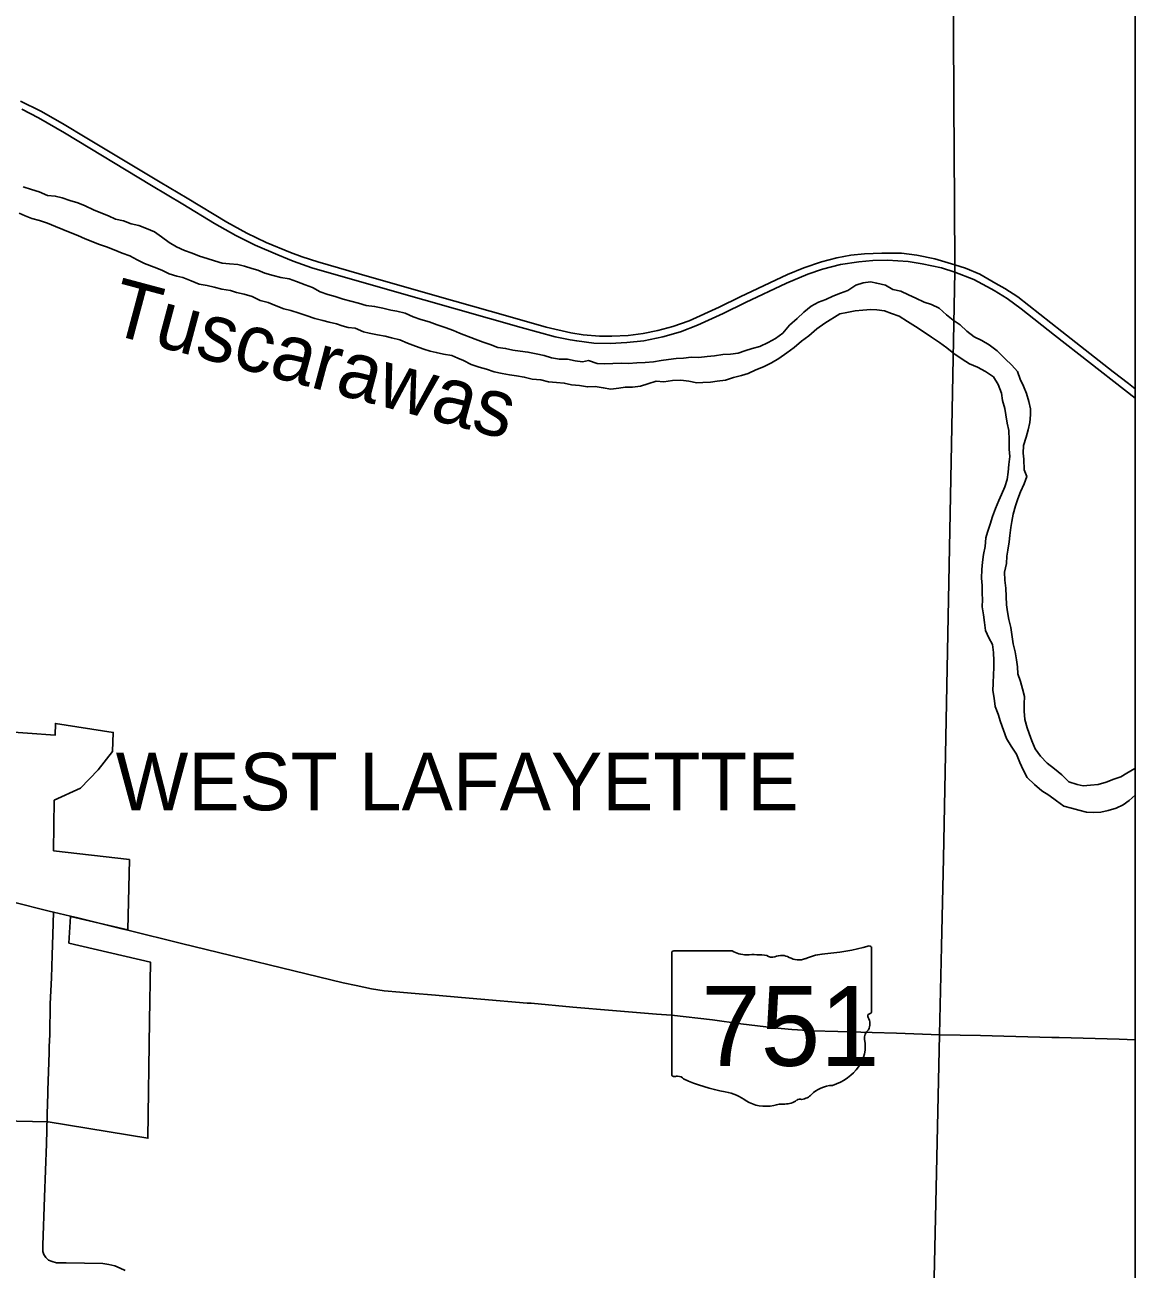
# Model space of a CAD drawing. Extents: x -6.3 to 34, y 0 to 22.
# Drawn here: x 10.934 to 12.189, y 11.89 to 13.296 of the extents above; entities that cross this region are included whole.
import ezdxf

# ---------------------------------------------------------------- set-up
doc = ezdxf.new("R2010")
doc.units = 0
for name, color, linetype in [('GM_X_Corporation', 7, 'Continuous'), ('GM_X_Corporation_Text', 7, 'Continuous'), ('GM_X_Major_River', 7, 'Continuous'), ('GM_X_Major_River_Text', 7, 'Continuous'), ('GM_X_State_Route', 7, 'Continuous'), ('GM_X_State_Shield', 7, 'Continuous'), ('GM_X_Township', 7, 'Continuous'), ('GM_X_US_Route', 7, 'Continuous'), ('SH_Text', 7, 'Continuous')]:
    doc.layers.add(name, color=color, linetype=linetype)

msp = doc.modelspace()

# ---------------------------------------------------------------- linework, layer by layer
at = {"layer": 'GM_X_Corporation'}
msp.add_lwpolyline([(10.8744, 12.5005), (10.9685, 12.4936), (10.9687, 12.5071), (11.0342, 12.4968), (11.0334, 12.4753), (11.0172, 12.4545), (10.997, 12.4338), (10.9674, 12.4203), (10.9667, 12.3631), (11.0524, 12.3532), (11.0506, 12.2737), (10.9859, 12.2887), (10.9841, 12.2589), (11.0763, 12.2372), (11.0753, 12.1709), (11.0733, 12.0382), (10.9606, 12.0567), (10.8895, 12.0582)], dxfattribs=at)
at = {"layer": 'GM_X_Major_River'}
for points in [[(11.6787, 12.9197), (11.6702, 12.9193), (11.6616, 12.9182), (11.6534, 12.9173), (11.6446, 12.9156), (11.6353, 12.9147), (11.6259, 12.9144), (11.6166, 12.9137), (11.6083, 12.9142), (11.5988, 12.9138), (11.5897, 12.9134), (11.5809, 12.9136), (11.5713, 12.9171), (11.5646, 12.9157), (11.556, 12.9169), (11.5474, 12.9187), (11.5384, 12.9186), (11.5295, 12.9203), (11.521, 12.9228), (11.5121, 12.9247), (11.5028, 12.9267), (11.494, 12.9277), (11.4857, 12.9289), (11.4776, 12.9308), (11.4688, 12.932), (11.4602, 12.9351), (11.4522, 12.9378), (11.4431, 12.9411), (11.4254, 12.9482), (11.4186, 12.9509), (11.4092, 12.9545), (11.4001, 12.9575), (11.391, 12.9608), (11.3819, 12.9635), (11.3731, 12.9663), (11.364, 12.9708), (11.3546, 12.9728), (11.3479, 12.974), (11.3388, 12.9763), (11.3295, 12.9782), (11.3201, 12.9794), (11.3113, 12.9819), (11.3027, 12.9842), (11.2939, 12.9864), (11.2851, 12.9894), (11.2765, 12.9917), (11.2679, 12.9947), (11.2593, 12.9995), (11.251, 13.0028), (11.2414, 13.0063), (11.233, 13.0096), (11.2237, 13.011), (11.2149, 13.013), (11.2055, 13.016), (11.1974, 13.0193), (11.1909, 13.0211), (11.1826, 13.0236), (11.1748, 13.0256), (11.1655, 13.0262), (11.1572, 13.0272), (11.1486, 13.0297), (11.1401, 13.0324), (11.1317, 13.0352), (11.1232, 13.0385), (11.1146, 13.0415), (11.1055, 13.0455), (11.0974, 13.0506), (11.0888, 13.057), (11.0807, 13.0624), (11.0718, 13.0662), (11.063, 13.0695), (11.0544, 13.0717), (11.0458, 13.075), (11.0367, 13.077), (11.0287, 13.0805), (11.0203, 13.084), (11.012, 13.0873), (11.0026, 13.0919), (10.994, 13.0954), (10.9852, 13.0979), (10.9766, 13.1009), (10.9686, 13.1029), (10.9598, 13.1034), (10.9504, 13.1079), (10.9416, 13.1104), (10.9325, 13.1134)], [(10.9279, 13.0838), (10.9347, 13.0807), (10.9422, 13.0777), (10.9508, 13.0754), (10.9599, 13.0722), (10.9687, 13.0684), (10.9773, 13.0651), (10.9856, 13.0618), (10.994, 13.0583), (11.0026, 13.0547), (11.0111, 13.0512), (11.0176, 13.0484), (11.0265, 13.0454), (11.0353, 13.0421), (11.0442, 13.0386), (11.0528, 13.0353), (11.0611, 13.031), (11.0694, 13.0269), (11.0804, 13.0226), (11.0889, 13.0191), (11.0975, 13.0151), (11.1061, 13.0123), (11.1129, 13.0111), (11.1222, 13.0073), (11.1311, 13.0032), (11.1402, 13.002), (11.1482, 13), (11.157, 12.9976), (11.1666, 12.9961), (11.1734, 12.9941), (11.1822, 12.9921), (11.1913, 12.9896), (11.2002, 12.9851), (11.2093, 12.9828), (11.2181, 12.9788), (11.227, 12.9755), (11.235, 12.9735), (11.2441, 12.9705), (11.2522, 12.968), (11.2618, 12.9645), (11.2711, 12.9622), (11.2781, 12.9605), (11.2865, 12.9585), (11.293, 12.9563), (11.2995, 12.9543), (11.3075, 12.9536), (11.3169, 12.9495), (11.3234, 12.948), (11.3327, 12.9463), (11.3413, 12.9446), (11.3485, 12.9429), (11.3579, 12.9404), (11.3665, 12.9368), (11.3758, 12.9333), (11.3852, 12.93), (11.3922, 12.9275), (11.3992, 12.9263), (11.4075, 12.9243), (11.4169, 12.9226), (11.4236, 12.9198), (11.4301, 12.9173), (11.4387, 12.9127), (11.4476, 12.9097), (11.4559, 12.9075), (11.4647, 12.9042), (11.4736, 12.9025), (11.4821, 12.901), (11.4899, 12.8998), (11.4987, 12.8984), (11.5076, 12.8961), (11.5174, 12.8952), (11.526, 12.8932), (11.5351, 12.8923), (11.5439, 12.8916), (11.5522, 12.8896), (11.561, 12.8889), (11.5701, 12.8872), (11.5789, 12.8878), (11.5879, 12.8864), (11.5963, 12.8847)], [(12.1236, 12.4382), (12.1142, 12.4412), (12.1061, 12.4489), (12.098, 12.4556), (12.0896, 12.462), (12.082, 12.4699), (12.076, 12.4785), (12.0722, 12.4872), (12.0693, 12.4955), (12.0669, 12.5022), (12.0644, 12.5113), (12.0635, 12.5207), (12.0637, 12.5292), (12.0639, 12.5375), (12.0617, 12.5463), (12.0595, 12.5544), (12.0566, 12.5629), (12.0562, 12.571), (12.0548, 12.579), (12.0534, 12.5881), (12.0513, 12.5971), (12.0484, 12.6153), (12.0463, 12.6244), (12.0446, 12.6332), (12.0437, 12.6412), (12.0431, 12.6503), (12.0427, 12.6599), (12.0419, 12.669), (12.0415, 12.6781), (12.0435, 12.6877), (12.0439, 12.696), (12.0451, 12.7028), (12.0465, 12.7122), (12.0472, 12.7192), (12.0484, 12.7283), (12.0496, 12.7351), (12.0511, 12.7434), (12.0536, 12.7528), (12.0566, 12.7609), (12.0593, 12.7689), (12.0636, 12.7776), (12.0666, 12.7862), (12.0636, 12.7934), (12.0632, 12.8056), (12.0626, 12.8123), (12.0628, 12.8212), (12.0659, 12.8306), (12.0681, 12.8389), (12.0701, 12.847), (12.0707, 12.8556), (12.0707, 12.8626), (12.0687, 12.8709), (12.0661, 12.8797), (12.0628, 12.888), (12.0591, 12.8962), (12.0562, 12.9048), (12.0496, 12.9117), (12.042, 12.9191), (12.0329, 12.9279), (12.024, 12.935), (12.0156, 12.9399), (12.007, 12.9439), (11.9987, 12.9503), (11.9913, 12.9575), (11.9835, 12.9626), (11.9757, 12.9688), (11.9675, 12.9762), (11.959, 12.9803), (11.9504, 12.983), (11.941, 12.9876), (11.9327, 12.9914), (11.9241, 12.9955), (11.9152, 12.9974), (11.9069, 13.0024), (11.897, 13.0045), (11.89, 13.006), (11.8818, 13.0049), (11.8735, 13.0022), (11.8643, 12.9961), (11.856, 12.9931), (11.8472, 12.9897), (11.8395, 12.9859), (11.8313, 12.983), (11.8228, 12.9787), (11.8146, 12.9716), (11.8071, 12.9645), (11.7984, 12.9569), (11.791, 12.9482), (11.7825, 12.9419), (11.7743, 12.9374), (11.765, 12.9329), (11.7563, 12.9307), (11.748, 12.928), (11.7403, 12.9256), (11.7317, 12.9244), (11.7229, 12.9238), (11.7136, 12.9224), (11.7054, 12.9218), (11.696, 12.9206), (11.6872, 12.921), (11.6787, 12.9197)], [(11.5963, 12.8847), (11.6056, 12.8858), (11.6128, 12.8869), (11.6211, 12.887), (11.6301, 12.8882), (11.6384, 12.8906), (11.6477, 12.8936), (11.6562, 12.8932), (11.6663, 12.8946), (11.6754, 12.8949), (11.6847, 12.8937), (11.6935, 12.892), (11.7005, 12.8921), (11.7091, 12.8925), (11.7168, 12.8936), (11.7259, 12.895), (11.7352, 12.898), (11.7442, 12.9001), (11.7517, 12.9026), (11.7604, 12.9066), (11.7689, 12.9098), (11.7779, 12.9146), (11.7862, 12.9193), (11.7954, 12.9259), (11.8036, 12.932), (11.8121, 12.9391), (11.8203, 12.9449), (11.8293, 12.9528), (11.8383, 12.9594), (11.8552, 12.97), (11.8632, 12.9714), (11.8726, 12.9731), (11.8813, 12.9739), (11.8904, 12.9748), (11.8971, 12.9744), (11.9057, 12.9734), (11.9135, 12.9704), (11.9223, 12.9671), (11.9317, 12.9613), (11.9409, 12.9554), (11.9495, 12.95), (11.9589, 12.9434), (11.968, 12.9373), (11.9761, 12.9316), (11.9842, 12.9252), (11.9936, 12.9186), (12.0017, 12.9135), (12.0108, 12.9097), (12.0199, 12.9046), (12.0288, 12.8985), (12.0343, 12.89), (12.0378, 12.8801), (12.0392, 12.8718), (12.0419, 12.863), (12.0428, 12.8558), (12.0444, 12.8464), (12.0461, 12.8381), (12.0467, 12.8275), (12.0468, 12.8171), (12.0472, 12.8088), (12.0463, 12.7997), (12.0456, 12.7911), (12.0444, 12.7828), (12.0417, 12.7742), (12.0379, 12.7656), (12.0351, 12.7588), (12.0313, 12.7499), (12.0278, 12.7408), (12.0251, 12.7322), (12.0223, 12.7233), (12.0203, 12.7168), (12.0194, 12.7069), (12.0177, 12.6978), (12.0165, 12.6892), (12.0156, 12.6809), (12.0154, 12.6713), (12.0163, 12.663), (12.0161, 12.6539), (12.0165, 12.6471), (12.0163, 12.6386), (12.0175, 12.6297), (12.0189, 12.6212), (12.02, 12.6121), (12.0237, 12.6038), (12.0277, 12.5961), (12.0288, 12.587), (12.0292, 12.5777), (12.0293, 12.5694), (12.0291, 12.5626), (12.0285, 12.5522), (12.0283, 12.5441), (12.0295, 12.5356), (12.0309, 12.5263), (12.0341, 12.5175), (12.0368, 12.5087), (12.0402, 12.4993), (12.0435, 12.49), (12.049, 12.4813), (12.0548, 12.4722), (12.0588, 12.4629), (12.0625, 12.4547)], [(12.0625, 12.4547), (12.067, 12.4461), (12.0751, 12.4382), (12.0835, 12.431), (12.0916, 12.4259), (12.1, 12.4195), (12.1083, 12.4136), (12.1169, 12.4111), (12.1255, 12.4089), (12.134, 12.4066), (12.1421, 12.4062), (12.1503, 12.4068), (12.1586, 12.4085), (12.1674, 12.4112), (12.1756, 12.4152), (12.1823, 12.4199), (12.189, 12.4259)], [(12.189, 12.4564), (12.1886, 12.4561), (12.1796, 12.4508), (12.1727, 12.4466), (12.1649, 12.4441), (12.1564, 12.4407), (12.1471, 12.4382), (12.1386, 12.4371), (12.1303, 12.4365), (12.1236, 12.4382)]]:
    msp.add_lwpolyline(points, dxfattribs=at)
at = {"layer": 'GM_X_State_Route'}
msp.add_line((10.9667, 12.2938), (10.9859, 12.2892), dxfattribs=at)
for points in [[(10.9667, 12.2938), (10.9619, 12.2948), (10.9199, 12.3056), (10.8417, 12.3246), (10.7958, 12.3362), (10.7559, 12.3462)], [(10.963, 12.19), (10.9642, 12.2196), (10.965, 12.2452), (10.9658, 12.2687), (10.9667, 12.2938)], [(10.9859, 12.2892), (10.9942, 12.2872), (11.0439, 12.275), (11.0508, 12.2733), (11.1111, 12.2585), (11.2941, 12.214), (11.3088, 12.2107), (11.326, 12.2071), (11.3405, 12.205), (11.3581, 12.2035), (11.371, 12.2023)], [(10.9609, 12.1135), (10.9616, 12.1351), (10.9618, 12.1416), (10.9623, 12.1557), (10.963, 12.19)], [(11.371, 12.2023), (11.3983, 12.1998), (11.4276, 12.1972), (11.4495, 12.1953), (11.5019, 12.1909), (11.5063, 12.1909), (11.5536, 12.1865), (11.5983, 12.1827), (11.6482, 12.1786), (11.665, 12.1772), (11.7113, 12.172), (11.7434, 12.1676), (11.781, 12.1629), (11.8012, 12.1611), (11.8074, 12.1607), (11.8239, 12.1596), (11.8529, 12.1588), (11.8919, 12.1578), (11.9194, 12.1572)], [(11.9194, 12.1572), (11.9682, 12.1553), (12.0141, 12.1542), (12.0407, 12.1536), (12.095, 12.1522), (12.1033, 12.152)], [(12.1033, 12.152), (12.171, 12.1503), (12.189, 12.1495)], [(10.9599, 12.079), (10.9601, 12.0871), (10.9603, 12.0925), (10.9609, 12.1135)], [(11.0476, 11.8889), (11.0421, 11.8914), (11.0359, 11.894), (11.0291, 11.8957), (11.0223, 11.8966), (10.9811, 11.8974), (10.9699, 11.8976), (10.965, 11.8991), (10.961, 11.9006), (10.9578, 11.9034), (10.9556, 11.9068), (10.9545, 11.9102), (10.9544, 11.9174), (10.9565, 11.9716), (10.9587, 12.0318), (10.9599, 12.079)]]:
    msp.add_lwpolyline(points, dxfattribs=at)
at = {"layer": 'GM_X_State_Shield'}
for p, q in [((11.6653, 12.2476), (11.6653, 12.1104)), ((11.7337, 12.2499), (11.6675, 12.2499)), ((11.8912, 12.1816), (11.8912, 12.2533)), ((11.8911, 12.1816), (11.8912, 12.1816))]:
    msp.add_line(p, q, dxfattribs=at)
for centre, major_axis, start_param, end_param in [((11.6679, 12.2479), (0.00262, 0), 1.712693, 3.28349), ((11.7494, 12.2659), (0.0254, 0), 4.042523, 4.731795), ((11.7578, 12.1729), (0.0911, 0), 1.404758, 1.657858), ((11.8413, 12.208), (0.0482, 0), 1.699011, 2.107814), ((11.8107, 12.4369), (0.2395, 0), 4.814394, 5.042369), ((11.8887, 12.2536), (0.00251, 0), 6.141152, 7.989035), ((11.7785, 12.2486), (0.00732, 0), 3.836095, 5.185415), ((11.7893, 12.2327), (0.0152, 0), 0.950623, 2.079405), ((11.8089, 12.2545), (0.0183, 0), 4.081561, 5.145723), ((11.8906, 12.1763), (0.00389, 0), 1.883978, 3.671073), ((11.8885, 12.1813), (0.00269, 0), 5.05454, 6.418171), ((11.8658, 12.1673), (0.0234, 0), 5.934695, 6.695948), ((11.8241, 12.1424), (0.0599, 0), 5.101752, 6.440018), ((11.9002, 12.1516), (0.017, 0), 2.387724, 3.262537), ((11.6679, 12.1101), (0.00264, 0), 3.00124, 4.508301), ((11.6683, 12.1242), (0.0201, 0), 4.665946, 4.897461), ((11.6724, 12.1025), (0.00726, 0), 0.519207, 1.627899), ((11.7641, 12.2257), (0.173, 0), 4.195997, 4.488961), ((11.8494, 12.0719), (0.0328, 0), 1.647645, 2.488434), ((11.7126, 12.0488), (0.0541, 0), 0.823519, 1.323587), ((11.7711, 12.1018), (0.0343, 0), 4.026481, 4.996735), ((11.7934, 12.0916), (0.0183, 0), 4.691044, 5.507374), ((11.81, 12.0783), (0.00515, 0), 1.147584, 2.315152), ((11.8078, 12.0971), (0.0194, 0), 4.937069, 5.64225), ((11.7909, 12.0544), (0.0282, 0), 1.495662, 1.94098)]:
    msp.add_ellipse(centre, major_axis=major_axis, ratio=0.8, start_param=start_param, end_param=end_param, dxfattribs=at)
at = {"layer": 'GM_X_Township'}
msp.add_lwpolyline([(12.189, 13.4049), (12.1616, 13.4057), (11.9837, 13.4105), (11.9832, 13.39), (11.9842, 13.205), (11.9845, 13.1562), (11.9852, 13.0258), (11.9853, 13.0174), (11.9723, 12.3546), (11.9703, 12.2549), (11.968, 12.1557), (11.9645, 11.9991), (11.9572, 11.6777), (11.9421, 11.0563), (11.9336, 10.5039), (11.9284, 10.2095), (11.9156, 9.9669)], dxfattribs=at)
at = {"layer": 'GM_X_US_Route'}
for points in [[(10.9295, 13.21), (10.9524, 13.1989), (10.9769, 13.185), (11.0043, 13.1685), (11.0478, 13.1425), (11.0871, 13.1187), (11.1177, 13.1004), (11.1625, 13.0734), (11.185, 13.0611), (11.2069, 13.0505), (11.2344, 13.039), (11.2477, 13.0343), (11.2654, 13.0286), (11.3119, 13.0151), (11.3896, 12.9929), (11.4203, 12.9841), (11.48, 12.9672), (11.5233, 12.9548), (11.5514, 12.9484), (11.5651, 12.9463), (11.5835, 12.9448), (11.5977, 12.9447), (11.6161, 12.9454), (11.633, 12.9475), (11.6495, 12.9509), (11.6665, 12.9554), (11.6849, 12.9619), (11.7188, 12.9774), (11.7428, 12.9889), (11.7962, 13.0143), (11.8144, 13.0219), (11.8346, 13.0288), (11.8518, 13.0333), (11.8677, 13.0361), (11.8831, 13.0375), (11.9029, 13.0386), (11.9248, 13.0383), (11.9421, 13.0361), (11.9625, 13.0322), (11.9854, 13.0254), (11.9971, 13.0213), (12.0133, 13.0145), (12.0315, 13.0043)], [(10.9307, 13.201), (10.9497, 13.1913), (10.9789, 13.1743), (11.0772, 13.115), (11.1128, 13.0937), (11.1487, 13.0721), (11.1725, 13.0585), (11.1944, 13.0475), (11.22, 13.0364), (11.231, 13.032), (11.2375, 13.0294), (11.2587, 13.0219), (11.3047, 13.0087), (11.3853, 12.9856), (11.4951, 12.9544), (11.5335, 12.9438), (11.5507, 12.9404), (11.5579, 12.9392), (11.5773, 12.9369), (11.5958, 12.9365), (11.6144, 12.9374), (11.6337, 12.9395), (11.6553, 12.9439), (11.6751, 12.9497), (11.6946, 12.957), (11.7233, 12.9703), (11.7487, 12.9825), (11.795, 13.0045), (11.8191, 13.0148), (11.8358, 13.0204), (11.8562, 13.0255), (11.8767, 13.0286), (11.8924, 13.03), (11.9092, 13.0304), (11.9325, 13.0291), (11.9482, 13.0265), (11.9702, 13.0218), (11.9854, 13.017), (12.0068, 13.0085), (12.0264, 12.9983), (12.0298, 12.9963)], [(12.0298, 12.9963), (12.0443, 12.9871), (12.0601, 12.9755), (12.0979, 12.9459), (12.1771, 12.8838), (12.189, 12.8744)], [(12.0315, 13.0043), (12.0419, 12.9986), (12.0565, 12.9889), (12.1061, 12.95), (12.164, 12.9042), (12.1814, 12.891), (12.189, 12.885)]]:
    msp.add_lwpolyline(points, dxfattribs=at)
at = {"layer": 'SH_Text'}
msp.add_lwpolyline([(1.8145, 20.7482), (12.189, 20.7482), (12.189, 9.3884), (1.8145, 9.3884)], close=True, dxfattribs=at)

# ---------------------------------------------------------------- texts
at = {"layer": 'GM_X_Corporation_Text'}
msp.add_text('WEST LAFAYETTE', height=0.064899, rotation=0, dxfattribs=at).set_placement((11.037, 12.4089))
at = {"layer": 'GM_X_Major_River_Text'}
msp.add_text('Tuscarawas', height=0.06489, rotation=345.0364, dxfattribs=at).set_placement((11.0268, 12.9484))
at = {"layer": 'GM_X_State_Shield'}
msp.add_text('751', height=0.09035, dxfattribs=at).set_placement((11.6986, 12.1201))

doc.saveas('drawing.dxf')
